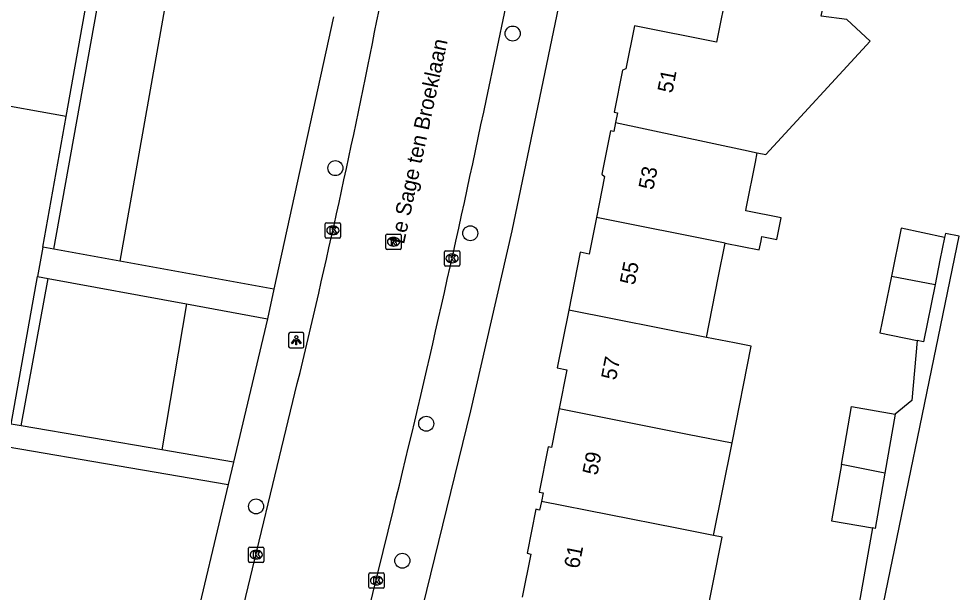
# Model space of a CAD drawing. Extents: x 161402 to 161933, y 381650 to 382313.
# Drawn here: x 161759.2 to 161820.4, y 381796.3 to 381833.7 of the extents above; entities that cross this region are included whole.
import ezdxf

# ---------------------------------------------------------------- set-up
doc = ezdxf.new("R2010")
doc.units = 0
for name, color, linetype in [('IMGEO_Boom', 7, 'Continuous'), ('IMGEO_Groenvoorziening', 7, 'Continuous'), ('IMGEO_Kolk', 7, 'Continuous'), ('IMGEO_Lichtpunt', 7, 'Continuous'), ('IMGEO_Openbare_ruimte_label', 7, 'Continuous'), ('IMGEO_Pand', 7, 'Continuous'), ('IMGEO_Pand_nummerreeks', 7, 'Continuous'), ('IMGEO_Rijbaan_lokaal_open', 7, 'Continuous'), ('IMGEO_Rioolput', 7, 'Continuous'), ('IMGEO_Voetpad_open', 7, 'Continuous')]:
    doc.layers.add(name, color=color, linetype=linetype)

msp = doc.modelspace()

# ---------------------------------------------------------------- linework, layer by layer
at = {"layer": 'IMGEO_Boom'}
for centre in [(161791.354, 381832.732), (161779.804, 381823.965), (161788.59, 381819.722), (161785.722, 381807.314), (161774.634, 381801.927), (161784.165, 381798.391)]:
    msp.add_circle(centre, 0.489, dxfattribs=at)
at = {"layer": 'IMGEO_Groenvoorziening'}
for points in [[(161768.9, 381835.705), (161765.769, 381817.905)], [(161770.1, 381815.124), (161768.488, 381805.603)]]:
    msp.add_lwpolyline(points, dxfattribs=at)
at = {"layer": 'IMGEO_Kolk'}
for p, q in [((161779.141, 381819.484), (161779.141, 381820.336)), ((161779.216, 381820.41), (161780.068, 381820.41)), ((161779.629, 381820.19), (161779.654, 381820.19)), ((161780.142, 381820.336), (161780.142, 381819.484)), ((161780.068, 381819.41), (161779.216, 381819.41)), ((161779.652, 381819.63), (161779.627, 381819.63)), ((161786.903, 381817.655), (161786.903, 381818.507)), ((161786.978, 381818.581), (161787.83, 381818.581)), ((161787.391, 381818.361), (161787.416, 381818.361)), ((161787.904, 381818.507), (161787.904, 381817.655)), ((161787.83, 381817.581), (161786.978, 381817.581)), ((161787.414, 381817.801), (161787.389, 381817.801)), ((161774.148, 381798.356), (161774.148, 381799.208)), ((161774.223, 381799.282), (161775.075, 381799.282)), ((161774.636, 381799.062), (161774.661, 381799.062)), ((161775.149, 381799.208), (161775.149, 381798.356)), ((161774.659, 381798.502), (161774.634, 381798.502)), ((161775.075, 381798.282), (161774.223, 381798.282)), ((161781.987, 381796.671), (161781.987, 381797.523)), ((161782.062, 381797.597), (161782.914, 381797.597)), ((161782.475, 381797.377), (161782.5, 381797.377)), ((161782.988, 381797.523), (161782.988, 381796.671)), ((161782.914, 381796.597), (161782.062, 381796.597)), ((161782.498, 381796.817), (161782.473, 381796.817))]:
    msp.add_line(p, q, dxfattribs=at)
for points in [[(161779.141, 381819.484), (161779.141, 381820.336)], [(161779.216, 381820.41), (161780.068, 381820.41)], [(161779.462, 381820.11), (161779.585, 381820.11), (161779.585, 381819.959), (161779.715, 381820.11), (161779.879, 381820.11), (161779.733, 381819.959), (161779.886, 381819.71), (161779.734, 381819.71), (161779.649, 381819.874), (161779.585, 381819.807), (161779.585, 381819.71), (161779.462, 381819.71), (161779.462, 381820.11)], [(161780.142, 381820.336), (161780.142, 381819.484)], [(161780.068, 381819.41), (161779.216, 381819.41)], [(161786.903, 381817.655), (161786.903, 381818.507)], [(161786.978, 381818.581), (161787.83, 381818.581)], [(161787.224, 381818.281), (161787.347, 381818.281), (161787.347, 381818.13), (161787.477, 381818.281), (161787.641, 381818.281), (161787.495, 381818.13), (161787.648, 381817.881), (161787.496, 381817.881), (161787.411, 381818.045), (161787.347, 381817.978), (161787.347, 381817.881), (161787.224, 381817.881), (161787.224, 381818.281)], [(161787.904, 381818.507), (161787.904, 381817.655)], [(161787.83, 381817.581), (161786.978, 381817.581)], [(161774.148, 381798.356), (161774.148, 381799.208)], [(161774.223, 381799.282), (161775.075, 381799.282)], [(161775.149, 381799.208), (161775.149, 381798.356)], [(161774.469, 381798.982), (161774.592, 381798.982), (161774.592, 381798.831), (161774.722, 381798.982), (161774.886, 381798.982), (161774.74, 381798.831), (161774.893, 381798.582), (161774.741, 381798.582), (161774.656, 381798.746), (161774.592, 381798.679), (161774.592, 381798.582), (161774.469, 381798.582), (161774.469, 381798.982)], [(161775.075, 381798.282), (161774.223, 381798.282)], [(161781.987, 381796.671), (161781.987, 381797.523)], [(161782.062, 381797.597), (161782.914, 381797.597)], [(161782.308, 381797.297), (161782.431, 381797.297), (161782.431, 381797.146), (161782.561, 381797.297), (161782.725, 381797.297), (161782.579, 381797.146), (161782.732, 381796.897), (161782.58, 381796.897), (161782.495, 381797.061), (161782.431, 381796.994), (161782.431, 381796.897), (161782.308, 381796.897), (161782.308, 381797.297)], [(161782.988, 381797.523), (161782.988, 381796.671)], [(161782.914, 381796.597), (161782.062, 381796.597)]]:
    msp.add_lwpolyline(points, dxfattribs=at)
for centre, start, end in [((161779.218, 381820.334), 91.55205, 178.44795), ((161779.218, 381820.334), 91.55205, 178.44795), ((161780.066, 381820.334), 1.55205, 88.44795), ((161780.066, 381820.334), 1.55205, 88.44795), ((161779.218, 381819.486), 181.55205, 268.44795), ((161779.218, 381819.486), 181.55205, 268.44795), ((161780.066, 381819.486), 271.55205, 358.44795), ((161780.066, 381819.486), 271.55205, 358.44795), ((161786.98, 381818.505), 91.55205, 178.44795), ((161786.98, 381818.505), 91.55205, 178.44795), ((161787.828, 381818.505), 1.55205, 88.44795), ((161787.828, 381818.505), 1.55205, 88.44795), ((161786.98, 381817.657), 181.55205, 268.44795), ((161786.98, 381817.657), 181.55205, 268.44795), ((161787.828, 381817.657), 271.55205, 358.44795), ((161787.828, 381817.657), 271.55205, 358.44795), ((161774.225, 381799.206), 91.55205, 178.44795), ((161774.225, 381799.206), 91.55205, 178.44795), ((161775.073, 381799.206), 1.55205, 88.44795), ((161775.073, 381799.206), 1.55205, 88.44795), ((161774.225, 381798.358), 181.55205, 268.44795), ((161774.225, 381798.358), 181.55205, 268.44795), ((161775.073, 381798.358), 271.55205, 358.44795), ((161775.073, 381798.358), 271.55205, 358.44795), ((161782.064, 381797.521), 91.55205, 178.44795), ((161782.064, 381797.521), 91.55205, 178.44795), ((161782.912, 381797.521), 1.55205, 88.44795), ((161782.912, 381797.521), 1.55205, 88.44795), ((161782.064, 381796.673), 181.55205, 268.44795), ((161782.064, 381796.673), 181.55205, 268.44795), ((161782.912, 381796.673), 271.55205, 358.44795), ((161782.912, 381796.673), 271.55205, 358.44795)]:
    msp.add_arc(centre, 0.0765, start, end, dxfattribs=at)
for centre, major_axis, ratio, start_param, end_param in [((161779.628, 381819.91), (-0.387, 0.002), 0.722429, 4.712389, 7.853982), ((161779.653, 381819.91), (-0.39, 0.002), 0.717154, 1.570796, 4.712389), ((161787.39, 381818.081), (-0.387, 0.002), 0.722429, 4.712389, 7.853982), ((161787.415, 381818.081), (-0.39, 0.002), 0.717154, 1.570796, 4.712389), ((161774.635, 381798.782), (-0.387, 0.002), 0.722429, 4.712389, 7.853982), ((161774.66, 381798.782), (-0.39, 0.002), 0.717154, 1.570796, 4.712389), ((161782.474, 381797.097), (-0.387, 0.002), 0.722429, 4.712389, 7.853982), ((161782.499, 381797.097), (-0.39, 0.002), 0.717154, 1.570796, 4.712389)]:
    msp.add_ellipse(centre, major_axis=major_axis, ratio=ratio, start_param=start_param, end_param=end_param, dxfattribs=at)
at = {"layer": 'IMGEO_Lichtpunt'}
for p, q in [((161776.755, 381813.153), (161776.755, 381812.346)), ((161776.755, 381813.153), (161776.755, 381812.346)), ((161777.657, 381813.248), (161776.849, 381813.248)), ((161777.657, 381813.248), (161776.849, 381813.248)), ((161777.751, 381812.346), (161777.751, 381813.153)), ((161777.751, 381812.346), (161777.751, 381813.153)), ((161776.849, 381812.252), (161777.657, 381812.252)), ((161776.849, 381812.252), (161777.657, 381812.252))]:
    msp.add_line(p, q, dxfattribs=at)
for points in [[(161777.129, 381812.817), (161777.168, 381812.789), (161776.98, 381812.527), (161776.942, 381812.554), (161777.129, 381812.817)], [(161777.231, 381812.769), (161777.278, 381812.769), (161777.278, 381812.447), (161777.231, 381812.447), (161777.231, 381812.769)], [(161777.341, 381812.789), (161777.379, 381812.816), (161777.566, 381812.554), (161777.527, 381812.526), (161777.341, 381812.789)]]:
    msp.add_lwpolyline(points, dxfattribs=at)
msp.add_circle((161777.254, 381812.951), 0.0994, dxfattribs=at)
for centre, start, end in [((161776.849, 381813.153), 90, 180), ((161776.849, 381813.153), 90, 180), ((161777.657, 381813.153), 0, 90), ((161777.657, 381813.153), 0, 90), ((161776.849, 381812.346), 180, 270), ((161776.849, 381812.346), 180, 270), ((161777.657, 381812.346), 270, 0), ((161777.657, 381812.346), 270, 360)]:
    msp.add_arc(centre, 0.0946, start, end, dxfattribs=at)
at = {"layer": 'IMGEO_Pand'}
for points in [[(161762.257, 381827.332), (161763.907, 381836.579)], [(161807.293, 381824.968), (161807.841, 381824.851), (161814.646, 381832.225), (161813.116, 381833.637), (161811.453, 381833.871), (161811.638, 381834.801), (161810.288, 381835.006), (161805.344, 381835.758), (161804.632, 381832.178), (161799.282, 381833.241), (161798.723, 381830.429), (161798.505, 381830.355), (161797.96, 381827.609), (161798.189, 381827.564), (161798.062, 381826.928)], [(161762.257, 381827.332), (161751.604, 381829.233)], [(161760.739, 381818.824), (161762.257, 381827.332)], [(161798.062, 381826.928), (161797.949, 381826.359), (161797.733, 381826.402), (161797.171, 381823.572), (161797.343, 381823.421), (161796.811, 381820.747)], [(161798.062, 381826.928), (161806.384, 381825.162), (161807.293, 381824.968)], [(161805.196, 381819.085), (161807.418, 381818.645), (161807.534, 381819.228), (161807.563, 381819.376), (161807.588, 381819.501), (161808.556, 381819.308), (161808.838, 381820.727), (161806.541, 381821.183), (161806.571, 381821.334), (161806.591, 381821.437), (161807.169, 381824.344), (161807.293, 381824.968)], [(161796.811, 381820.747), (161796.337, 381818.362), (161795.751, 381818.479), (161795.003, 381814.718)], [(161805.196, 381819.085), (161796.811, 381820.747)], [(161819.493, 381819.448), (161816.664, 381820.054), (161816.035, 381816.937)], [(161819.493, 381819.448), (161819.195, 381817.973), (161818.873, 381816.374)], [(161760.739, 381818.824), (161760.397, 381816.906)], [(161803.974, 381812.939), (161804.745, 381816.817), (161805.196, 381819.085)], [(161758.68, 381807.283), (161760.397, 381816.906)], [(161816.035, 381816.937), (161815.286, 381813.226), (161817.7, 381812.739)], [(161816.035, 381816.937), (161818.873, 381816.374)], [(161818.873, 381816.374), (161818.122, 381812.654), (161817.7, 381812.739)], [(161795.003, 381814.718), (161794.255, 381810.955), (161794.881, 381810.83), (161794.378, 381808.3)], [(161803.974, 381812.939), (161795.003, 381814.718)], [(161805.649, 381806.066), (161806.9, 381812.359), (161805.797, 381812.578), (161803.974, 381812.939)], [(161794.378, 381808.3), (161793.874, 381805.762), (161793.674, 381805.802), (161793.09, 381802.862), (161793.332, 381802.814), (161793.221, 381802.252)], [(161794.378, 381808.3), (161802.744, 381806.642), (161805.649, 381806.066)], [(161812.777, 381804.654), (161813.439, 381808.425), (161816.282, 381807.926)], [(161816.282, 381807.926), (161815.609, 381804.092)], [(161804.448, 381800.027), (161805.649, 381806.066)], [(161812.777, 381804.654), (161812.135, 381800.996), (161814.791, 381800.53)], [(161815.609, 381804.092), (161812.777, 381804.654)], [(161815.609, 381804.092), (161814.978, 381800.497), (161814.791, 381800.53)], [(161793.221, 381802.252), (161793.109, 381801.69), (161792.864, 381801.739), (161792.295, 381798.873), (161792.53, 381798.826), (161791.972, 381796.02)], [(161804.448, 381800.027), (161802.044, 381800.503), (161793.221, 381802.252)], [(161802.645, 381793.903), (161803.759, 381793.682), (161804.998, 381799.918), (161804.448, 381800.027)]]:
    msp.add_lwpolyline(points, dxfattribs=at)
at = {"layer": 'IMGEO_Rijbaan_lokaal_open'}
for points in [[(161789.643, 381828.457), (161790.913, 381834.452)], [(161773.151, 381792.659), (161773.259, 381793.093), (161777.321, 381809.926)], [(161778.621, 381781.514), (161783.566, 381801.642)]]:
    msp.add_lwpolyline(points, dxfattribs=at)
for centre, radius, start, end in [((161271.221, 381945.362), 523.363, 347.66578, 350.17353), ((161240.294, 381940.065), 552.57, 346.378, 348.88744), ((160980.917, 381997.64), 826.233, 346.27755, 348.1843)]:
    msp.add_arc(centre, radius, start, end, dxfattribs=at)
at = {"layer": 'IMGEO_Rioolput'}
for p, q in [((161783.091, 381818.745), (161783.091, 381819.597)), ((161783.166, 381819.671), (161784.018, 381819.671)), ((161783.579, 381819.451), (161783.604, 381819.451)), ((161784.092, 381819.597), (161784.092, 381818.745)), ((161784.018, 381818.671), (161783.166, 381818.671)), ((161783.602, 381818.891), (161783.577, 381818.891))]:
    msp.add_line(p, q, dxfattribs=at)
for points in [[(161783.091, 381818.745), (161783.091, 381819.597)], [(161783.166, 381819.671), (161784.018, 381819.671)], [(161783.68, 381819.369), (161783.428, 381819.371), (161783.428, 381818.971)], [(161783.606, 381819.29), (161783.552, 381819.29), (161783.552, 381819.209)], [(161784.092, 381819.597), (161784.092, 381818.745)], [(161784.018, 381818.671), (161783.166, 381818.671)], [(161783.428, 381818.971), (161783.552, 381818.971), (161783.552, 381819.133), (161783.563, 381819.133)], [(161783.552, 381819.209), (161783.604, 381819.209)], [(161783.61, 381819.104), (161783.681, 381818.971), (161783.821, 381818.971), (161783.756, 381819.097)]]:
    msp.add_lwpolyline(points, dxfattribs=at)
for centre, radius, start, end in [((161783.168, 381819.595), 0.0765, 91.55205, 178.44795), ((161783.168, 381819.595), 0.0765, 91.55205, 178.44795), ((161783.612, 381819.194), 0.0964, 77.00612, 93.18647), ((161783.626, 381819.251), 0.0378, 276.66336, 79.67722), ((161783.679, 381819.259), 0.109, 350.36119, 89.41601), ((161783.677, 381819.259), 0.112, 277.58423, 350.98172), ((161784.016, 381819.595), 0.0765, 1.55205, 88.44795), ((161784.016, 381819.595), 0.0765, 1.55205, 88.44795), ((161783.168, 381818.747), 0.0765, 181.55205, 268.44795), ((161783.168, 381818.747), 0.0765, 181.55205, 268.44795), ((161783.562, 381819.08), 0.0533, 26.02933, 88.69889), ((161783.588, 381819.398), 0.19, 274.7715, 282.96867), ((161783.661, 381819.044), 0.108, 29.51342, 73.79051), ((161784.016, 381818.747), 0.0765, 271.55205, 358.44795), ((161784.016, 381818.747), 0.0765, 271.55205, 358.44795)]:
    msp.add_arc(centre, radius, start, end, dxfattribs=at)
for centre, major_axis, ratio, start_param, end_param in [((161783.578, 381819.171), (-0.387, 0.002), 0.722429, 4.712389, 7.853982), ((161783.603, 381819.171), (-0.39, 0.002), 0.717154, 1.570796, 4.712389)]:
    msp.add_ellipse(centre, major_axis=major_axis, ratio=ratio, start_param=start_param, end_param=end_param, dxfattribs=at)
at = {"layer": 'IMGEO_Voetpad_open'}
for points in [[(161778.698, 381768.78), (161781.039, 381777.203), (161788.629, 381808.145), (161791.311, 381819.878), (161794.918, 381837.231), (161795.748, 381841.221), (161796.717, 381845.885), (161801.214, 381871.562), (161802.683, 381881.227), (161808.066, 381922.168), (161810.3, 381942.403)], [(161761.449, 381818.694), (161764.644, 381836.45)], [(161779.683, 381833.819), (161775.802, 381816.071)], [(161814.602, 381791.103), (161814.613, 381791.164), (161820.446, 381819.524), (161819.545, 381819.706), (161819.493, 381819.448)], [(161761.449, 381818.694), (161760.739, 381818.824)], [(161765.769, 381817.905), (161761.449, 381818.694)], [(161775.802, 381816.071), (161765.769, 381817.905)], [(161759.331, 381807.171), (161761.088, 381816.779)], [(161760.397, 381816.906), (161761.088, 381816.779)], [(161761.088, 381816.779), (161770.1, 381815.124)], [(161775.802, 381816.071), (161775.382, 381814.154)], [(161770.1, 381815.124), (161775.382, 381814.154)], [(161775.382, 381814.154), (161773.157, 381804.803)], [(161817.7, 381812.739), (161817.369, 381808.831), (161816.282, 381807.926)], [(161751.647, 381809.088), (161751.227, 381807.036), (161772.812, 381803.355)], [(161759.331, 381807.171), (161758.68, 381807.283)], [(161768.488, 381805.603), (161759.331, 381807.171)], [(161773.157, 381804.803), (161768.488, 381805.603)], [(161773.157, 381804.803), (161772.812, 381803.355)], [(161772.812, 381803.355), (161770.352, 381793.016)], [(161814.791, 381800.53), (161813.929, 381795.618)]]:
    msp.add_lwpolyline(points, dxfattribs=at)

# ---------------------------------------------------------------- texts
at = {"layer": 'IMGEO_Openbare_ruimte_label'}
msp.add_text('Le Sage ten Broeklaan', height=1, rotation=77.88124, dxfattribs=at).set_placement((161784.271, 381818.964))
at = {"layer": 'IMGEO_Pand_nummerreeks'}
for s, p in [('51', (161801.754, 381828.81)), ('53', (161800.516, 381822.504)), ('55', (161799.299, 381816.308)), ('57', (161798.081, 381810.113)), ('59', (161796.864, 381803.917)), ('61', (161795.668, 381797.831))]:
    msp.add_text(s, height=1, rotation=78.88483, dxfattribs=at).set_placement(p)

doc.saveas('drawing.dxf')
